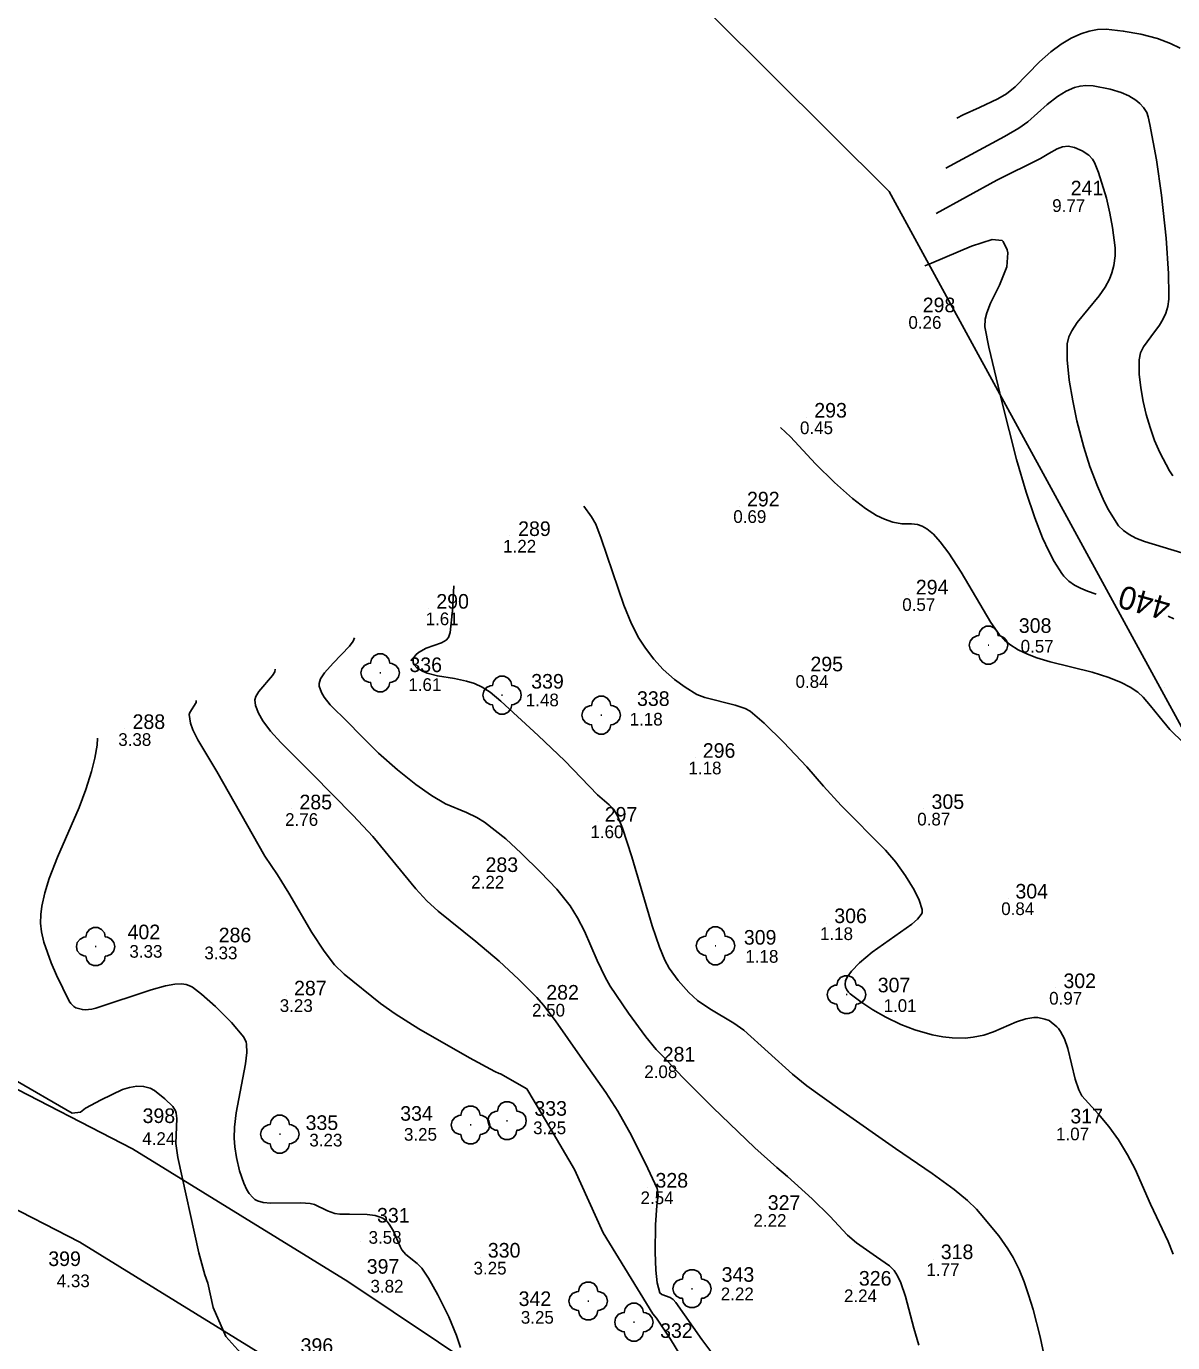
# Model space of a CAD drawing. Extents: x -792549 to -792339, y -1111914 to -1111617.
# Drawn here: x -792528.5 to -792498.69, y -1111704.34 to -1111670.1 of the extents above; entities that cross this region are included whole.
import ezdxf

# ---------------------------------------------------------------- set-up
doc = ezdxf.new("R2010")
doc.units = 0
for name, color, linetype in [('Vrstva 1', 7, 'Continuous'), ('Vrstva 31', 7, 'Continuous'), ('Vrstva 32', 7, 'Continuous'), ('Vrstva 33', 7, 'Continuous'), ('Vrstva 41', 7, 'Continuous'), ('Vrstva 44', 7, 'Continuous'), ('Vrstva 47', 7, 'Continuous'), ('Vrstva 48', 7, 'Continuous'), ('Vrstva 49', 7, 'Continuous'), ('Vrstva 50', 7, 'Continuous')]:
    doc.layers.add(name, color=color, linetype=linetype)

# ---------------------------------------------------------------- blocks, each defined once
blk = doc.blocks.new('SC6231')
at = {"layer": 'Vrstva 1'}
blk.add_line((0, 0), (0, 0), dxfattribs=at)
blk = doc.blocks.new('3$1300')
at = {"layer": 'Vrstva 1'}
for points in [[(20, 0), (19, -4.3), (16.2, -7.8), (12.2, -9.7), (10, -10), (9, -14.3), (6.2, -17.8), (2.2, -19.7), (-2.3, -19.7), (-6.3, -17.8), (-9.1, -14.3), (-10.1, -10), (-12.3, -9.7), (-16.3, -7.8), (-19.1, -4.3), (-20.1, 0), (-19.1, 4.3), (-16.3, 7.8), (-12.3, 9.7), (-10.1, 10), (-9.1, 14.3), (-6.3, 17.8), (-2.3, 19.7), (2.2, 19.7), (6.2, 17.8), (9, 14.3), (10, 10), (12.2, 9.7), (16.2, 7.8), (19, 4.3), (20, 0)], [(-0.5, 0), (0, 0), (0.5, 0)]]:
    blk.add_lwpolyline(points, dxfattribs=at)
blk = doc.blocks.new('3$1301')
at = {"layer": 'Vrstva 1'}
for points in [[(20, 0), (19, -4.3), (16.2, -7.8), (12.2, -9.7), (10, -10), (9, -14.3), (6.2, -17.8), (2.2, -19.7), (-2.3, -19.7), (-6.3, -17.8), (-9.1, -14.3), (-10.1, -10), (-12.3, -9.7), (-16.3, -7.8), (-19.1, -4.3), (-20.1, 0), (-19.1, 4.3), (-16.3, 7.8), (-12.3, 9.7), (-10.1, 10), (-9.1, 14.3), (-6.3, 17.8), (-2.3, 19.7), (2.2, 19.7), (6.2, 17.8), (9, 14.3), (10, 10), (12.2, 9.7), (16.2, 7.8), (19, 4.3), (20, 0)], [(-0.5, 0), (0, 0), (0.5, 0)]]:
    blk.add_lwpolyline(points, dxfattribs=at)

msp = doc.modelspace()

# ---------------------------------------------------------------- linework, layer by layer
at = {"layer": 'Vrstva 31'}
for points in [[(-792500.676, -1111684.877), (-792500.905, -1111684.799), (-792501.091, -1111684.72), (-792501.246, -1111684.636), (-792501.39, -1111684.535), (-792501.518, -1111684.406), (-792501.569, -1111684.338), (-792501.77, -1111684.019), (-792501.909, -1111683.758), (-792502.073, -1111683.405), (-792502.278, -1111682.89), (-792502.504, -1111682.218), (-792502.75, -1111681.373), (-792503.136, -1111679.865), (-792503.474, -1111678.445), (-792503.572, -1111677.918), (-792503.568, -1111677.716), (-792503.527, -1111677.556), (-792503.432, -1111677.304), (-792503.194, -1111676.832), (-792503.005, -1111676.354), (-792502.98, -1111675.997), (-792502.993, -1111675.917), (-792503.102, -1111675.698), (-792503.126, -1111675.677), (-792503.388, -1111675.648), (-792503.925, -1111675.821), (-792504.959, -1111676.267), (-792505.132, -1111676.331)], [(-792498.657, -1111685.517), (-792498.811, -1111685.442)]]:
    msp.add_lwpolyline(points, dxfattribs=at)
at = {"layer": 'Vrstva 32'}
for points in [[(-792499.26, -1111678.176), (-792499.035, -1111677.876), (-792498.943, -1111677.726), (-792498.868, -1111677.567), (-792498.815, -1111677.394), (-792498.791, -1111677.202), (-792498.786, -1111677.088), (-792498.798, -1111676.535), (-792498.863, -1111675.611), (-792498.981, -1111674.493), (-792499.111, -1111673.571), (-792499.281, -1111672.652), (-792499.328, -1111672.453), (-792499.366, -1111672.345), (-792499.45, -1111672.21), (-792499.541, -1111672.11), (-792499.648, -1111672.021), (-792499.833, -1111671.908), (-792500.029, -1111671.823), (-792500.313, -1111671.736), (-792500.756, -1111671.651), (-792500.952, -1111671.637), (-792501.099, -1111671.655), (-792501.245, -1111671.697), (-792501.456, -1111671.79), (-792501.687, -1111671.93), (-792501.956, -1111672.134), (-792502.46, -1111672.584), (-792502.688, -1111672.75), (-792503.062, -1111672.971), (-792504.586, -1111673.792)], [(-792498.685, -1111681.794), (-792498.77, -1111681.667), (-792499.026, -1111681.191), (-792499.16, -1111680.874), (-792499.279, -1111680.539), (-792499.379, -1111680.2), (-792499.461, -1111679.857), (-792499.522, -1111679.508), (-792499.56, -1111679.15), (-792499.565, -1111678.775), (-792499.523, -1111678.597), (-792499.445, -1111678.44), (-792499.26, -1111678.176)], [(-792498.673, -1111702.043), (-792498.809, -1111701.712), (-792499.264, -1111700.744), (-792499.664, -1111699.83), (-792499.861, -1111699.454), (-792500.095, -1111699.069), (-792500.349, -1111698.718), (-792500.616, -1111698.398), (-792501.049, -1111697.923), (-792501.134, -1111697.767), (-792501.223, -1111697.488), (-792501.419, -1111696.695), (-792501.504, -1111696.441), (-792501.607, -1111696.251), (-792501.659, -1111696.172), (-792501.703, -1111696.124), (-792501.906, -1111695.963), (-792502.017, -1111695.926), (-792502.196, -1111695.888), (-792502.305, -1111695.885), (-792502.51, -1111695.917), (-792502.753, -1111695.996), (-792503.349, -1111696.261), (-792503.602, -1111696.344), (-792503.881, -1111696.4), (-792504.091, -1111696.42), (-792504.425, -1111696.415), (-792504.671, -1111696.388), (-792504.948, -1111696.336), (-792505.394, -1111696.208), (-792505.761, -1111696.063), (-792506.149, -1111695.878), (-792506.488, -1111695.687), (-792506.799, -1111695.478), (-792507.077, -1111695.267), (-792507.12, -1111695.228), (-792507.168, -1111695.165), (-792507.198, -1111695.095), (-792507.208, -1111695.019), (-792507.195, -1111694.934), (-792507.152, -1111694.836), (-792507.041, -1111694.678), (-792506.833, -1111694.459), (-792506.507, -1111694.189), (-792505.478, -1111693.457), (-792505.33, -1111693.329), (-792505.234, -1111693.209), (-792505.209, -1111693.166), (-792505.205, -1111693.077), (-792505.285, -1111692.836), (-792505.416, -1111692.564), (-792505.636, -1111692.197), (-792505.887, -1111691.844), (-792506.155, -1111691.535), (-792507.313, -1111690.373), (-792507.77, -1111689.864), (-792508.208, -1111689.362), (-792508.813, -1111688.722), (-792509.316, -1111688.23), (-792509.679, -1111687.92), (-792509.812, -1111687.846), (-792510.068, -1111687.758), (-792510.856, -1111687.563), (-792511.066, -1111687.481), (-792511.372, -1111687.296), (-792511.649, -1111687.091), (-792511.937, -1111686.831), (-792512.182, -1111686.564), (-792512.405, -1111686.281), (-792512.571, -1111686.019), (-792512.765, -1111685.643), (-792512.968, -1111685.155), (-792513.553, -1111683.421), (-792513.695, -1111683.051), (-792513.801, -1111682.859), (-792514.004, -1111682.582)], [(-792505.291, -1111704.407), (-792505.422, -1111703.968), (-792505.637, -1111703.147), (-792505.759, -1111702.784), (-792505.845, -1111702.602), (-792505.935, -1111702.464), (-792506.058, -1111702.346), (-792506.389, -1111702.107), (-792506.915, -1111701.746), (-792507.143, -1111701.551), (-792507.606, -1111701.052), (-792508.063, -1111700.604), (-792508.705, -1111700.025), (-792508.986, -1111699.784), (-792509.555, -1111699.272), (-792510.651, -1111698.228), (-792511.431, -1111697.444), (-792511.966, -1111696.877), (-792512.127, -1111696.715), (-792512.396, -1111696.392), (-792512.843, -1111695.775), (-792513.319, -1111695.068), (-792513.453, -1111694.834), (-792513.654, -1111694.404), (-792513.991, -1111693.637), (-792514.166, -1111693.292), (-792514.362, -1111692.978), (-792514.708, -1111692.549), (-792515.129, -1111692.103), (-792515.636, -1111691.607), (-792516.037, -1111691.24), (-792516.587, -1111690.806), (-792516.787, -1111690.68), (-792517.059, -1111690.556), (-792517.598, -1111690.325), (-792517.965, -1111690.108), (-792518.371, -1111689.826), (-792518.853, -1111689.446), (-792519.341, -1111689.013), (-792519.815, -1111688.544), (-792520.141, -1111688.203), (-792520.6, -1111687.751), (-792520.759, -1111687.552), (-792520.829, -1111687.433), (-792520.89, -1111687.269), (-792520.89, -1111687.194), (-792520.853, -1111687.079), (-792520.75, -1111686.917), (-792520.528, -1111686.667), (-792520.103, -1111686.226), (-792520.004, -1111686.092), (-792519.971, -1111686.008)], [(-792516.176, -1111697.349), (-792516.21, -1111697.342), (-792516.32, -1111697.29), (-792516.981, -1111696.934), (-792518.294, -1111696.176), (-792518.912, -1111695.788), (-792519.291, -1111695.519), (-792520.237, -1111694.756), (-792520.489, -1111694.517), (-792520.762, -1111694.163), (-792521.078, -1111693.671), (-792521.675, -1111692.649), (-792521.973, -1111692.176), (-792522.298, -1111691.686), (-792523.546, -1111689.49), (-792524.042, -1111688.661), (-792524.172, -1111688.398), (-792524.233, -1111688.229), (-792524.266, -1111688.005), (-792524.25, -1111687.948), (-792524.091, -1111687.691), (-792524.083, -1111687.642)], [(-792531.018, -1111696.194), (-792530.405, -1111696.621), (-792528.894, -1111697.453), (-792527.31, -1111698.376), (-792527.094, -1111698.351), (-792526.964, -1111698.246)], [(-792516.176, -1111697.349), (-792515.484, -1111697.744), (-792514.864, -1111698.792), (-792514.243, -1111699.839), (-792513.505, -1111701.483), (-792512.209, -1111703.591)], [(-792523.78, -1111702.8), (-792523.862, -1111702.576), (-792524.014, -1111702.009), (-792524.564, -1111699.53), (-792524.618, -1111699.166), (-792524.592, -1111698.515), (-792524.606, -1111698.378), (-792524.622, -1111698.31), (-792524.692, -1111698.201), (-792524.903, -1111697.999), (-792525.168, -1111697.788), (-792525.283, -1111697.724), (-792525.454, -1111697.678), (-792525.634, -1111697.673), (-792525.818, -1111697.702), (-792526, -1111697.761), (-792526.555, -1111698.026), (-792526.964, -1111698.246)], [(-792522.401, -1111705.199), (-792522.766, -1111704.792), (-792523.312, -1111704.182), (-792523.641, -1111703.432), (-792523.78, -1111702.8)], [(-792511.48, -1111704.694), (-792511.75, -1111704.25), (-792512.117, -1111703.708), (-792512.209, -1111703.591)]]:
    msp.add_lwpolyline(points, dxfattribs=at)
at = {"layer": 'Vrstva 33'}
for points in [[(-792498.491, -1111670.673), (-792498.747, -1111670.547), (-792499.088, -1111670.422), (-792499.52, -1111670.309), (-792499.975, -1111670.226), (-792500.424, -1111670.179), (-792500.641, -1111670.187), (-792500.86, -1111670.228), (-792501.082, -1111670.3), (-792501.326, -1111670.412), (-792501.589, -1111670.566), (-792501.858, -1111670.764), (-792502.156, -1111671.026), (-792502.783, -1111671.672), (-792503.01, -1111671.854), (-792503.241, -1111671.99), (-792503.713, -1111672.214), (-792504.141, -1111672.405), (-792504.306, -1111672.49)], [(-792501.379, -1111679.306), (-792501.43, -1111678.777), (-792501.432, -1111678.36), (-792501.391, -1111678.182), (-792501.317, -1111678.024), (-792501.176, -1111677.809), (-792500.604, -1111677.112), (-792500.447, -1111676.886), (-792500.337, -1111676.675), (-792500.272, -1111676.51), (-792500.219, -1111676.326), (-792500.19, -1111676.07), (-792500.19, -1111675.862), (-792500.253, -1111675.338), (-792500.322, -1111674.961), (-792500.413, -1111674.576), (-792500.622, -1111673.905), (-792500.725, -1111673.642), (-792500.772, -1111673.558), (-792500.873, -1111673.454), (-792501.047, -1111673.342), (-792501.245, -1111673.256), (-792501.404, -1111673.222), (-792501.552, -1111673.239), (-792501.698, -1111673.293), (-792501.909, -1111673.407), (-792502.127, -1111673.539), (-792503.259, -1111674.107), (-792504.839, -1111674.971)], [(-792498.455, -1111683.8), (-792499.424, -1111683.505), (-792499.649, -1111683.414), (-792499.825, -1111683.322), (-792499.969, -1111683.221), (-792500.096, -1111683.092), (-792500.161, -1111683), (-792500.355, -1111682.681), (-792500.468, -1111682.465), (-792500.649, -1111682.063), (-792500.844, -1111681.548), (-792501.002, -1111681.048), (-792501.182, -1111680.36), (-792501.291, -1111679.84), (-792501.379, -1111679.306)], [(-792498.399, -1111688.751), (-792498.76, -1111688.394), (-792499.045, -1111688.057), (-792499.267, -1111687.774), (-792499.457, -1111687.553), (-792499.6, -1111687.426), (-792499.799, -1111687.289), (-792500.028, -1111687.167), (-792500.349, -1111687.037), (-792500.78, -1111686.905), (-792501.874, -1111686.636), (-792502.219, -1111686.529), (-792502.469, -1111686.43), (-792502.709, -1111686.317), (-792502.929, -1111686.18), (-792503.068, -1111686.069), (-792503.197, -1111685.932), (-792503.42, -1111685.613), (-792504.187, -1111684.302), (-792504.511, -1111683.804), (-792504.734, -1111683.509), (-792504.911, -1111683.316), (-792505.081, -1111683.175), (-792505.203, -1111683.105), (-792505.325, -1111683.06), (-792505.482, -1111683.043), (-792505.735, -1111683.043), (-792505.968, -1111683), (-792506.186, -1111682.924), (-792506.394, -1111682.824), (-792506.681, -1111682.642), (-792507.016, -1111682.384), (-792507.486, -1111681.971), (-792507.983, -1111681.483), (-792508.63, -1111680.784), (-792508.886, -1111680.54)], [(-792503.796, -1111700.872), (-792504.025, -1111700.648), (-792504.373, -1111700.358), (-792504.944, -1111699.942), (-792505.902, -1111699.289), (-792507.348, -1111698.278), (-792508.202, -1111697.66), (-792508.574, -1111697.356), (-792509.84, -1111696.211), (-792510.104, -1111696.029), (-792510.729, -1111695.664), (-792511.046, -1111695.441), (-792511.273, -1111695.236), (-792511.552, -1111694.922), (-792511.781, -1111694.605), (-792511.9, -1111694.392), (-792512.039, -1111694.059), (-792512.225, -1111693.503), (-792512.753, -1111691.706), (-792512.999, -1111690.962), (-792513.13, -1111690.643), (-792513.232, -1111690.469), (-792513.342, -1111690.353), (-792513.65, -1111690.09), (-792514.501, -1111689.208), (-792515.192, -1111688.549), (-792516.163, -1111687.658), (-792516.441, -1111687.421), (-792516.646, -1111687.292), (-792516.847, -1111687.199), (-792517.054, -1111687.132), (-792517.37, -1111687.071), (-792517.811, -1111687.001), (-792518.075, -1111686.931), (-792518.203, -1111686.879), (-792518.347, -1111686.792), (-792518.425, -1111686.703), (-792518.441, -1111686.647), (-792518.439, -1111686.543), (-792518.376, -1111686.452), (-792518.301, -1111686.387), (-792518.107, -1111686.278), (-792517.705, -1111686.135), (-792517.587, -1111686.069), (-792517.528, -1111686.003), (-792517.495, -1111685.922), (-792517.484, -1111685.874), (-792517.423, -1111685.299), (-792517.387, -1111684.655)], [(-792510.494, -1111704.847), (-792510.939, -1111704.262), (-792511.614, -1111703.301), (-792511.678, -1111703.22), (-792511.759, -1111703.172), (-792511.973, -1111703.09), (-792512.024, -1111703.05), (-792512.093, -1111702.784), (-792512.132, -1111702.46), (-792512.151, -1111701.99), (-792512.141, -1111701.275), (-792512.104, -1111700.779), (-792512.069, -1111700.505), (-792512.086, -1111700.379), (-792512.099, -1111700.335), (-792512.342, -1111699.816), (-792512.769, -1111698.958), (-792513.123, -1111698.319), (-792513.431, -1111697.833), (-792514.102, -1111696.892), (-792514.74, -1111695.973), (-792515.057, -1111695.561), (-792515.23, -1111695.365), (-792515.7, -1111694.884), (-792516.205, -1111694.42), (-792516.812, -1111693.911), (-792517.796, -1111693.12), (-792518.087, -1111692.853), (-792518.375, -1111692.536), (-792519.494, -1111691.177), (-792520.007, -1111690.631), (-792521.072, -1111689.544), (-792521.888, -1111688.735), (-792522.155, -1111688.436), (-792522.355, -1111688.169), (-792522.47, -1111687.967), (-792522.542, -1111687.769), (-792522.562, -1111687.62), (-792522.539, -1111687.534), (-792522.46, -1111687.407), (-792522.102, -1111686.986), (-792522.045, -1111686.892), (-792522.029, -1111686.826)], [(-792523.081, -1111699.252), (-792523.098, -1111699.021), (-792523.093, -1111698.736), (-792523.05, -1111698.362), (-792522.806, -1111697.092), (-792522.772, -1111696.793), (-792522.777, -1111696.582), (-792522.788, -1111696.524), (-792522.844, -1111696.394), (-792523.171, -1111696.018), (-792523.582, -1111695.602), (-792523.945, -1111695.281), (-792524.183, -1111695.098), (-792524.231, -1111695.07), (-792524.349, -1111695.029), (-792524.468, -1111695.013), (-792524.64, -1111695.02), (-792524.888, -1111695.062), (-792525.258, -1111695.166), (-792526.694, -1111695.64), (-792526.801, -1111695.667), (-792526.977, -1111695.684), (-792527.047, -1111695.68), (-792527.219, -1111695.637), (-792527.271, -1111695.597), (-792527.35, -1111695.518), (-792527.392, -1111695.458), (-792527.723, -1111694.786), (-792527.862, -1111694.467), (-792528.05, -1111693.927), (-792528.113, -1111693.654), (-792528.132, -1111693.433), (-792528.128, -1111693.21), (-792528.102, -1111692.985), (-792528.027, -1111692.639), (-792527.913, -1111692.267), (-792527.696, -1111691.716), (-792527.134, -1111690.424), (-792526.954, -1111689.954), (-792526.805, -1111689.489), (-792526.72, -1111689.141), (-792526.665, -1111688.801), (-792526.651, -1111688.623)], [(-792517.213, -1111704.468), (-792517.316, -1111704.156), (-792517.519, -1111703.673), (-792517.801, -1111703.098), (-792518.043, -1111702.662), (-792518.214, -1111702.403), (-792518.335, -1111702.288), (-792518.635, -1111702.049), (-792518.736, -1111701.933), (-792518.785, -1111701.843), (-792518.967, -1111701.422), (-792519.067, -1111701.258), (-792519.122, -1111701.194), (-792519.231, -1111701.105), (-792519.299, -1111701.076), (-792519.432, -1111701.035), (-792519.637, -1111701.008), (-792520.103, -1111700.997), (-792520.351, -1111701.002), (-792520.478, -1111700.984), (-792520.671, -1111700.912), (-792521.012, -1111700.748), (-792521.124, -1111700.725), (-792521.369, -1111700.703), (-792522.145, -1111700.718), (-792522.34, -1111700.7), (-792522.489, -1111700.652), (-792522.558, -1111700.617), (-792522.613, -1111700.567), (-792522.706, -1111700.46), (-792522.765, -1111700.369), (-792522.848, -1111700.196), (-792522.956, -1111699.874), (-792523.039, -1111699.525), (-792523.081, -1111699.252)], [(-792501.937, -1111705.135), (-792502.139, -1111704.188), (-792502.32, -1111703.485), (-792502.437, -1111703.098), (-792502.554, -1111702.761), (-792502.685, -1111702.438), (-792502.836, -1111702.128), (-792502.974, -1111701.9), (-792503.213, -1111701.567), (-792503.693, -1111700.985), (-792503.796, -1111700.872)]]:
    msp.add_lwpolyline(points, dxfattribs=at)
at = {"layer": 'Vrstva 41'}
msp.add_lwpolyline([(-792536.737, -1111643.89), (-792506.06, -1111674.4), (-792485.77, -1111711.57), (-792480.39, -1111721.44), (-792475.74, -1111713.71), (-792475.81, -1111712.09), (-792485.77, -1111711.57)], dxfattribs=at)
at = {"layer": 'Vrstva 47'}
for p, q in [((-792538.56, -1111692.69), (-792525.74, -1111699.3)), ((-792527.11, -1111701.73), (-792539.64, -1111695.31)), ((-792525.74, -1111699.3), (-792520.14, -1111702.75)), ((-792521.58, -1111705.14), (-792527.11, -1111701.73)), ((-792520.14, -1111702.75), (-792515.07, -1111706.14))]:
    msp.add_line(p, q, dxfattribs=at)

# ---------------------------------------------------------------- block references
at = {"layer": 'Vrstva 44', "xscale": 0.025, "yscale": 0.025000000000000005}
for name, p in [('3$1301', (-792503.48, -1111686.2)), ('3$1301', (-792519.3, -1111686.92)), ('3$1301', (-792516.13, -1111687.5)), ('3$1301', (-792513.55, -1111688.02)), ('3$1300', (-792526.7, -1111694.04)), ('3$1301', (-792510.58, -1111694.02)), ('3$1301', (-792507.17, -1111695.29)), ('3$1301', (-792516.95, -1111698.68)), ('3$1301', (-792516, -1111698.57)), ('3$1301', (-792521.91, -1111698.92)), ('3$1301', (-792511.19, -1111702.94)), ('3$1301', (-792513.89, -1111703.26)), ('3$1301', (-792512.7, -1111703.81))]:
    msp.add_blockref(name, p, dxfattribs=at)
at = {"layer": 'Vrstva 47', "xscale": 0.1, "yscale": 0.10000000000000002}
msp.add_blockref('SC6231', (-792520.14, -1111702.75), dxfattribs=at)
at = {"layer": 'Vrstva 48', "xscale": 0.1, "yscale": 0.10000000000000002}
for p in [(-792501.65, -1111674.49), (-792505.39, -1111677.53), (-792508.21, -1111680.27), (-792509.96, -1111682.58), (-792515.93, -1111683.35), (-792505.55, -1111684.87), (-792518.04, -1111685.24), (-792503.48, -1111686.2), (-792519.3, -1111686.92), (-792508.31, -1111686.87), (-792516.13, -1111687.5), (-792498.9, -1111687.3), (-792513.55, -1111688.02), (-792525.94, -1111688.38), (-792511.11, -1111689.12), (-792521.6, -1111690.46), (-792505.16, -1111690.45), (-792513.66, -1111690.78), (-792516.76, -1111692.09), (-792502.96, -1111692.78), (-792507.69, -1111693.43), (-792526.7, -1111694.04), (-792523.7, -1111693.93), (-792510.58, -1111694.02), (-792501.73, -1111695.11), (-792521.74, -1111695.3), (-792515.18, -1111695.42), (-792507.17, -1111695.29), (-792512.26, -1111697.02), (-792516, -1111698.57), (-792521.91, -1111698.92), (-792516.95, -1111698.68), (-792501.55, -1111698.64), (-792525.74, -1111699.3), (-792512.34, -1111700.3), (-792509.42, -1111700.89), (-792527.11, -1111701.73), (-792519.8, -1111701.72), (-792516.7, -1111702.13), (-792504.92, -1111702.17), (-792520.14, -1111702.75), (-792511.19, -1111702.94), (-792507.05, -1111702.85), (-792513.89, -1111703.26), (-792512.7, -1111703.81)]:
    msp.add_blockref('SC6231', p, dxfattribs=at)

# ---------------------------------------------------------------- texts
at = {"layer": 'Vrstva 31'}
msp.add_text('440', height=0.6, rotation=164.3581, dxfattribs=at).set_placement((-792498.704, -1111684.99))
at = {"layer": 'Vrstva 49'}
for s, p in [('241', (-792501.343, -1111674.5)), ('298', (-792505.191, -1111677.54)), ('293', (-792508.011, -1111680.28)), ('292', (-792509.761, -1111682.59)), ('289', (-792515.713, -1111683.36)), ('294', (-792505.37, -1111684.88)), ('290', (-792517.841, -1111685.25)), ('308', (-792502.691, -1111685.88)), ('336', (-792518.541, -1111686.9)), ('295', (-792508.111, -1111686.88)), ('339', (-792515.373, -1111687.33)), ('338', (-792512.621, -1111687.78)), ('288', (-792525.741, -1111688.38)), ('296', (-792510.911, -1111689.13)), ('285', (-792521.401, -1111690.47)), ('305', (-792504.961, -1111690.46)), ('297', (-792513.461, -1111690.79)), ('283', (-792516.561, -1111692.1)), ('304', (-792502.78, -1111692.79)), ('306', (-792507.491, -1111693.43)), ('402', (-792525.871, -1111693.85)), ('286', (-792523.501, -1111693.93)), ('309', (-792509.843, -1111693.99)), ('302', (-792501.531, -1111695.12)), ('287', (-792521.541, -1111695.31)), ('282', (-792514.981, -1111695.42)), ('307', (-792506.361, -1111695.23)), ('281', (-792511.953, -1111697.03)), ('398', (-792525.481, -1111698.63)), ('334', (-792518.78, -1111698.57)), ('333', (-792515.291, -1111698.44)), ('335', (-792521.241, -1111698.81)), ('317', (-792501.351, -1111698.64)), ('328', (-792512.141, -1111700.31)), ('327', (-792509.221, -1111700.89)), ('331', (-792519.383, -1111701.22)), ('399', (-792527.933, -1111702.35)), ('330', (-792516.501, -1111702.13)), ('318', (-792504.721, -1111702.17)), ('397', (-792519.651, -1111702.55)), ('343', (-792510.421, -1111702.76)), ('326', (-792506.851, -1111702.86)), ('342', (-792515.701, -1111703.39)), ('332', (-792512.021, -1111704.22)), ('396', (-792521.371, -1111704.61))]:
    msp.add_text(s, height=0.38, dxfattribs=at).set_placement(p)
at = {"layer": 'Vrstva 50'}
for s, p in [('9.77', (-792501.823, -1111674.93)), ('0.26', (-792505.563, -1111677.97)), ('0.45', (-792508.383, -1111680.71)), ('0.69', (-792510.117, -1111683.02)), ('1.22', (-792516.103, -1111683.79)), ('0.57', (-792505.723, -1111685.31)), ('1.61', (-792518.119, -1111685.68)), ('0.57', (-792502.644, -1111686.393)), ('1.61', (-792518.569, -1111687.39)), ('0.84', (-792508.499, -1111687.31)), ('1.48', (-792515.513, -1111687.79)), ('1.18', (-792512.813, -1111688.29)), ('3.38', (-792526.113, -1111688.82)), ('1.18', (-792511.283, -1111689.56)), ('2.76', (-792521.773, -1111690.9)), ('0.87', (-792505.333, -1111690.89)), ('1.60', (-792513.833, -1111691.22)), ('2.22', (-792516.933, -1111692.53)), ('0.84', (-792503.149, -1111693.22)), ('1.18', (-792507.863, -1111693.87)), ('3.33', (-792525.823, -1111694.33)), ('3.33', (-792523.873, -1111694.37)), ('1.18', (-792509.803, -1111694.46)), ('3.23', (-792521.913, -1111695.74)), ('1.01', (-792506.209, -1111695.74)), ('0.97', (-792501.903, -1111695.55)), ('2.50', (-792515.353, -1111695.86)), ('2.08', (-792512.433, -1111697.46)), ('3.25', (-792515.323, -1111698.92)), ('4.24', (-792525.489, -1111699.2)), ('3.23', (-792521.143, -1111699.24)), ('3.25', (-792518.683, -1111699.09)), ('1.07', (-792501.723, -1111699.08)), ('2.54', (-792512.529, -1111700.74)), ('2.22', (-792509.593, -1111701.33)), ('3.58', (-792519.603, -1111701.77)), ('3.25', (-792516.873, -1111702.57)), ('1.77', (-792505.093, -1111702.61)), ('4.33', (-792527.713, -1111702.9)), ('3.82', (-792519.553, -1111703.04)), ('2.22', (-792510.443, -1111703.24)), ('2.24', (-792507.239, -1111703.29)), ('3.25', (-792515.643, -1111703.85))]:
    msp.add_text(s, height=0.33, dxfattribs=at).set_placement(p)

doc.saveas('drawing.dxf')
